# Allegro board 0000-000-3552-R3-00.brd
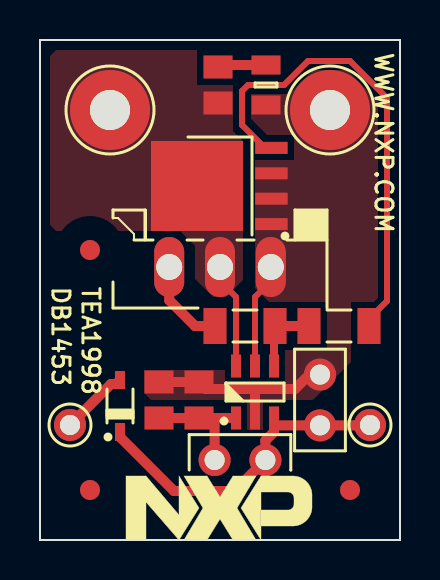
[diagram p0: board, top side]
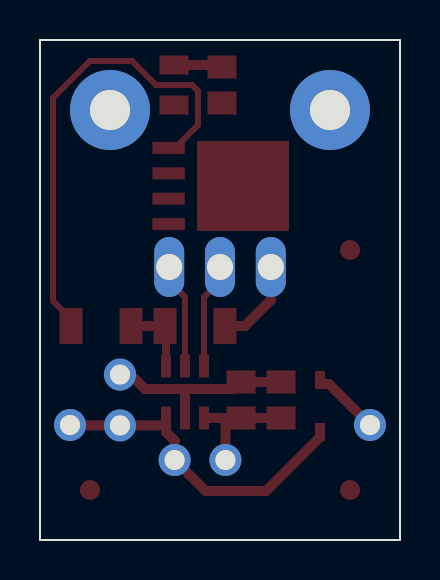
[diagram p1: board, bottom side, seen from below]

Outline 18 x 25 mm; copper layers: TOP, BOTTOM. Coordinates in mm from the lower left corner of the outline.
Outline path: 0,25 18,25 18,0 0,0 0,25

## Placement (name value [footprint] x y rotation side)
C1  10 nF  [CAPC2013X145X115Y145C180N]  7.95 7 90 top
C2  1 uF  [CAPC2013X145X115Y145C180N]  5.95 7 90 top
C3  10 nF  [CAPC2013X145X115Y145C180N]  8.9 22.75 90 top
D1  BAS316  [SOD2513X110X50Y90C260N]  4 6.7 90 top
E1  AWG18  [WH_AWG18_0160_0100_0220]  16.5 5.75 0 top
E2  AWG12  [WH_AWG12_0400_0200_0440]  3.5 21.5 0 top
E3  AWG12  [WH_AWG12_0400_0200_0440]  14.5 21.5 0 top
E4  AWG18  [WH_AWG18_0160_0100_0220]  1.5 5.75 0 top
JP1  22-28-4020  [CONT_MOL_22-28-4020_2PMS_L_ISO]  10 4 180 top
JP2  22-28-4020  [CONT_MOL_22-28-4020_2PMS_L_ISO]  14 7 90 top
NOREF  -  [unnamed]  2.5 14.5 0 top
NOREF#2  -  [#2]  -10 -10 90 top
NOREF#3  -  [#2]  -10 125 90 top
NOREF#4  -  [#2]  -10 135 0 top
NOREF#5  -  [#2]  9 1.6 0 top
NOREF#6  -  [#2]  0 25 0 top
NOREF#7  -  [#2]  -10 135 0 top
NOREF#8  -  [unnamed]  2.5 2.5 0 top
NOREF#9  -  [#2]  0 0 90 top
NOREF#10  -  [unnamed]  15.5 2.5 0 top
Q1  PSMN7R0-60YS  [TO127P600X120-5X60Y162C372N]  9 17.7 180 top
Q2  PSMN4R3-100PS  [TO220RRV254W85P3L1065T485H1960TB_AT1_ISO]  9 16.5 0 top
R1  0 R  [RESC3216X75X180Y115C300N]  14.95 10.7 180 top
R2  0 R  [RESC3216X75X180Y115C300N]  10.25 10.7 0 top
R3  10 R  [RESC2013X84X145Y95C200N]  11.3 22.75 90 top
U1  TEA1993T  [SOT95P275X110-6X115Y50C260N]  10.75 7.4 90 top

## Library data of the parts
C1-C3 = CAPN_02_01_A
D1 = DIO_02_01_A
E1-E4 = WH_01_01_A
JP1 JP2 = JMP_02_01_B_NO-NR
Q1 = MFN_05_01_A
Q2 = MFN_03_01_A
R1-R3 = RES_02_01_A
U1 = NXP_TEA1993_TSOP6

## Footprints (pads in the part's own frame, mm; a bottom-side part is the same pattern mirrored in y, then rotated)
CAPC2013X145X115Y145C180N
  rect 1.15x1.45 smd: 1(-0.9,0) 2(0.9,0)
CONT_MOL_22-28-4020_2PMS_L_ISO
  round 1.6 hole 1: 1(-1.27,0) 2(1.27,0)
RESC2013X84X145Y95C200N
  rect 0.95x1.45 smd: 1(-1,0) 2(1,0)
RESC3216X75X180Y115C300N
  rect 1.15x1.8 smd: 1(-1.5,0) 2(1.5,0)
SOD2513X110X50Y90C260N
  rect 0.9x0.5 smd: 1(-1.3,0) 2(1.3,0)
SOT95P275X110-6X115Y50C260N
  rect 1.15x0.5 smd: 1(-1.3,0.95) 2(-1.3,0) 3(-1.3,-0.95) 4(1.3,-0.95) 5(1.3,0) 6(1.3,0.95)
TO127P600X120-5X60Y162C372N
  rect 1.62x0.6 smd: 1(-2.57,1.905) 2(-2.57,0.635) 3(-2.57,-0.635) 4(-2.57,-1.905)
  rect 4.6x4.5 smd: 5(1.15,0)
TO220RRV254W85P3L1065T485H1960TB_AT1_ISO
  oval 1.5x3 hole 1.3: 1(-2.54,-2.85) 2(0,-2.85) 3(2.54,-2.85)
unnamed
  round 1 smd: (0,0)
WH_AWG12_0400_0200_0440
  round 4 hole 2: 1(0,0)
WH_AWG18_0160_0100_0220
  round 1.6 hole 1: 1(0,0)

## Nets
CAP: C1.1 C2.1 JP1.2 U1.1(CAP)
DRAIN: C3.1 E2.1 Q1.5(D) Q2.2(D) U1.6(DRAIN)
SOURCE: C1.2 C2.2 E3.1 JP2.2 Q1.1(S1) Q1.2(S2) Q1.3(S3) Q2.3(S) R3.1 U1.2(GND) U1.5(SOURCE)
XV: D1.1(C) E1.1 JP1.1 JP2.1 U1.3(XV)
N6706455: Q1.4(G) R1.1
N6706664: R1.2 R2.2 U1.4(GATE)
N6708555: C3.2 R3.2
N6709881: Q2.1(G) R2.1
N6711825: D1.2(A) E4.1

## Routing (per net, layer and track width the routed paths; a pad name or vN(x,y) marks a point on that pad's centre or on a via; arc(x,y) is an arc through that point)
CAP: length 6
  TOP w0.5: C2.1 C1.1 8.73,6.1 ; 8.73,6.1 JP1.2 ; 8.73,6.1 U1.1
DRAIN: length 5.3
  TOP w0.3: U1.6 9.8,12.15 9,12.95 Q2.2
SOURCE: length 14.7
  TOP w0.3: Q2.3 11.54,12.94 10.75,12.15 U1.5
  TOP w0.5: 13.55,8.1 13.3,8.1 12.75,7.55 10.75,7.55 ; 10.75,7.55 8.3,7.55 C1.2 C2.2 ; 10.75,7.55 U1.2
XV: length 16.4
  TOP w0.5: 11.7,5.73 11.7,5.4 11.27,4.97 JP1.1 9.72,2.45 6.7,2.45 4,5.15 D1.1 ; 11.7,5.73 JP2.1 16.48,5.73 E1.1 ; 11.7,5.73 U1.3
N6706455: length 24.1
  TOP w0.3: Q1.4 11.24,19.61 10.1,20.75 10.1,22.45 10.4,22.75 12.2,22.75 13.4,23.95 15.5,23.95 17.35,22.1 17.35,11.95 16.45,11.05 R1.1
N6706664: length 3.7
  TOP w0.4: R2.2 11.7,10.65 U1.4
  TOP w0.5: R2.2 R1.2
N6708555: length 2.4
  TOP w0.5: R3.2 9,23.75 C3.2
N6709881: length 4.5
  TOP w0.5: Q2.1 6.46,11.99 7.75,10.7 R2.1
N6711825: length 3.4
  TOP w0.5: E4.1 3.55,7.8 3.8,7.8 D1.2

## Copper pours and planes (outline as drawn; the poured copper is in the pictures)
DRAIN on TOP: 8.65,12.15 7.75,13.05 7.75,14.7 7,15.45 0.8,15.45 0.5,15.75 0.5,24.2 0.8,24.5 7.85,24.5 7.85,22.75 9.65,22.75 9.65,20.45 10.15,19.95 10.15,13 9.3,12.15
SOURCE on TOP: 10.75,12.6 11.45,11.9 14.35,11.9 14.35,9.5 12.25,9.5 12.25,7.8 9.25,7.8 9.25,8.5 5.2,8.5 5.2,7.35 5.55,7 10.35,7 10.35,5.5 11.15,5.5 11.15,7 13.65,7 15.55,8.9 15.55,11.9 16.7,11.9 16.9,12.1 16.9,21.95 15.35,23.5 13.65,23.5 12.45,22.3 10.55,22.3 10.55,21.05 11.35,20.25 12.7,20.25 12.7,19 10.75,19

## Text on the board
Ref Des/Silkscreen Top: DB1453 | TEA1998 | WWW.NXP.COM
PANEL: SCORING | GROOVE
PCB-NUMBER_ALL: 0000-000-35523
User.7: SIGNAL_1 COMP SIDE 2A1
User.8: SIGNAL_2 SOLDER SIDE 2A2
User.9: ASSEMBLY | TOP
User.10: ASSEMBLY | BOTTOM
User.11: SOLDERMASK_1 COMP SIDE 2A00
User.12: SOLDERMASK_2 SOLDER SIDE 2B00
User.13: SOLDERPASTE_1 COMP SIDE 2A0
User.14: SOLDERPASTE_2 SOLDER SIDE 2B0
User.15: DRILL DRAWING
User.16: SILKSCREEN_1 COMP SIDE 2A000
User.17: SILKSCREEN_2 SOLDER SIDE 2B000
User.18: MILLING PLATED
User.19: MILLING NON PLATING
User.26: FIGURE | SIZE | 1.0000 | 1.3000 | 2.0000 | DRILL CHART: TOP to BOTTOM | ALL UNITS ARE IN MILLIMETERS | PLATED | QTY | 6 | 3 | 2 | 11 | TOTAL HOLES:
User.27: PANEL DRAWING
User.28: 9999-000-35523
